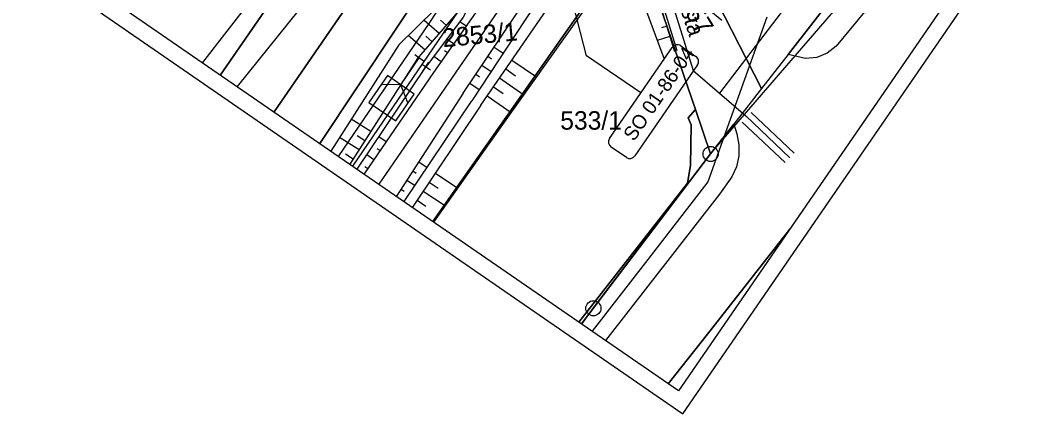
# Model space of a CAD drawing. Extents: x -558195 to -557985, y -1073457 to -1073198.
# Drawn here: x -558195.2 to -558102.7, y -1073456.6 to -1073420.3 of the extents above; entities that cross this region are included whole.
import ezdxf

# ---------------------------------------------------------------- set-up
doc = ezdxf.new("R2010")
doc.units = 0
for name, color, linetype in [('bubliny', 7, 'Continuous'), ('CETIN', 7, 'Continuous'), ('DWG-zabzař', 7, 'Continuous'), ('GasNet', 7, 'Continuous'), ('Kolej', 7, 'Continuous'), ('Komunikace', 7, 'Continuous'), ('Návěst místo trati', 7, 'Continuous'), ('Pasportizace VO Rapotín', 7, 'Continuous'), ('Plot - zábradlí', 7, 'Continuous'), ('Přejezd - štěrkové lože', 7, 'Continuous'), ('Rámeček', 7, 'Continuous'), ('Rámeček stavby', 7, 'Continuous'), ('Sonda - šrafa - vrstevnice', 7, 'Continuous'), ('Svazek obcí údolí Desné', 7, 'Continuous'), ('Svazek obcí-zabezpečovací', 7, 'Continuous'), ('Terén', 7, 'Continuous'), ('Vrstva 15', 7, 'Continuous'), ('Vrstva 18', 7, 'Continuous'), ('ŠPVS - kanalizace', 7, 'Continuous')]:
    doc.layers.add(name, color=color, linetype=linetype)

msp = doc.modelspace()

# ---------------------------------------------------------------- linework, layer by layer
at = {"layer": 'bubliny'}
for p, q in [((-558142.954, -1073423.635), (-558147.804, -1073404.729)), ((-558137.931, -1073427.051), (-558142.954, -1073423.635))]:
    msp.add_line(p, q, dxfattribs=at)
for points in [[(-558140.819, -1073431.245), (-558135.042, -1073422.858)], [(-558134.256, -1073422.713), (-558132.858, -1073423.675)], [(-558132.713, -1073424.462), (-558138.489, -1073432.85)], [(-558139.276, -1073432.995), (-558140.674, -1073432.032)]]:
    msp.add_lwpolyline(points, dxfattribs=at)
for centre, start, end in [((-558134.577, -1073423.179), 55.44273, 145.44273), ((-558133.179, -1073424.141), 325.44273, 55.44273), ((-558140.353, -1073431.566), 145.44273, 235.44273), ((-558138.955, -1073432.529), 235.44273, 325.44273)]:
    msp.add_arc(centre, 0.566, start, end, dxfattribs=at)
at = {"layer": 'CETIN'}
msp.add_lwpolyline([(-558151.47, -1073374.57), (-558151.89, -1073380.18), (-558153.51, -1073389.8), (-558157.95, -1073398.34), (-558171.64, -1073415.56), (-558178.389, -1073424.233)], dxfattribs=at)
at = {"layer": 'DWG-zabzař'}
msp.add_line((-558154.78, -1073419.51), (-558164.522, -1073433.785), dxfattribs=at)
at = {"layer": 'GasNet'}
msp.add_lwpolyline([(-558126.32, -1073420.06), (-558131.77, -1073435.23), (-558137.3, -1073442.38), (-558142.436, -1073448.999)], dxfattribs=at)
at = {"layer": 'Kolej'}
msp.add_lwpolyline([(-558162.085, -1073435.464), (-558155.66, -1073426.127), (-558147.216, -1073413.854), (-558143.692, -1073408.727), (-558141.06, -1073404.904), (-558137.302, -1073399.438), (-558134.569, -1073395.461), (-558131.717, -1073391.307), (-558124.893, -1073381.375), (-558115.4, -1073367.564), (-558106.183, -1073354.164), (-558097.487, -1073341.511), (-558095.261, -1073338.268), (-558090.946, -1073331.927), (-558084.696, -1073322.399), (-558079.035, -1073313.091), (-558076.876, -1073309.237)], dxfattribs=at)
at = {"layer": 'Komunikace'}
for points in [[(-558134.582, -1073423.154), (-558136.753, -1073416.165), (-558138.246, -1073411.366), (-558139.293, -1073408.016), (-558139.888, -1073406.031), (-558138.651, -1073404.246), (-558137.19, -1073402.13), (-558136.19, -1073405.354), (-558136.385, -1073405.515), (-558134.943, -1073410.228), (-558133.406, -1073415.122), (-558132.477, -1073418.012), (-558131.667, -1073419.37), (-558130.464, -1073420.348)], [(-558139.888, -1073406.031), (-558140.066, -1073406.285), (-558138.481, -1073411.422), (-558136.982, -1073416.266), (-558134.819, -1073423.23)]]:
    msp.add_lwpolyline(points, dxfattribs=at)
at = {"layer": 'Návěst místo trati'}
for p, q in [((-558157.974, -1073424.108), (-558158.798, -1073423.542)), ((-558160.086, -1073426.297), (-558158.386, -1073423.825)), ((-558158.179, -1073424.355), (-558157.355, -1073424.921)), ((-558158.05, -1073425.05), (-558157.484, -1073424.226))]:
    msp.add_line(p, q, dxfattribs=at)
for points in [[(-558160.086, -1073426.297), (-558161.322, -1073425.446), (-558163.023, -1073427.918), (-558160.551, -1073429.618), (-558158.851, -1073427.147), (-558160.086, -1073426.297)], [(-558159.419, -1073427.972), (-558160.086, -1073426.297), (-558161.89, -1073426.272)]]:
    msp.add_lwpolyline(points, dxfattribs=at)
at = {"layer": 'Pasportizace VO Rapotín'}
msp.add_lwpolyline([(-558143.374, -1073448.353), (-558142.291, -1073446.842), (-558131.5, -1073432.67), (-558118.796, -1073417.905), (-558090.893, -1073382.398), (-558083.8, -1073372.96), (-558076.467, -1073364.463), (-558070.931, -1073355.845), (-558066.74, -1073349.792), (-558061.514, -1073327.752)], dxfattribs=at)
for centre in [(-558131.5, -1073432.67), (-558142.318, -1073446.888)]:
    msp.add_circle(centre, 0.698, dxfattribs=at)
at = {"layer": 'Plot - zábradlí'}
for points in [[(-558150.682, -1073429.948), (-558139.407, -1073414.153), (-558135.827, -1073423.839)], [(-558157.022, -1073438.951), (-558150.682, -1073429.948)]]:
    msp.add_lwpolyline(points, dxfattribs=at)
at = {"layer": 'Přejezd - štěrkové lože'}
for p, q in [((-558154.06, -1073420.903), (-558154.641, -1073420.494)), ((-558154.635, -1073421.72), (-558154.877, -1073421.55)), ((-558155.211, -1073422.538), (-558155.837, -1073422.098)), ((-558155.786, -1073423.356), (-558156.046, -1073423.173)), ((-558151.481, -1073422.835), (-558150.644, -1073423.398)), ((-558156.362, -1073424.174), (-558157.034, -1073423.701)), ((-558152.597, -1073424.495), (-558151.744, -1073425.069)), ((-558152.039, -1073423.665), (-558151.701, -1073423.893)), ((-558153.156, -1073425.324), (-558152.811, -1073425.557)), ((-558153.714, -1073426.154), (-558152.843, -1073426.74)), ((-558161.433, -1073431.55), (-558162.106, -1073431.089)), ((-558162.563, -1073433.201), (-558163.227, -1073432.746)), ((-558161.998, -1073432.376), (-558162.265, -1073432.192)), ((-558158.431, -1073433.397), (-558157.648, -1073433.905)), ((-558163.128, -1073434.025), (-558163.392, -1073433.845)), ((-558158.975, -1073434.236), (-558158.667, -1073434.436)), ((-558159.519, -1073435.076), (-558158.764, -1073435.565)), ((-558160.063, -1073435.915), (-558159.767, -1073436.107))]:
    msp.add_line(p, q, dxfattribs=at)
for points in [[(-558142.117, -1073403.477), (-558143.754, -1073404.051), (-558146.162, -1073407.17), (-558149.304, -1073412.355), (-558152.838, -1073417.196), (-558154.313, -1073420.055), (-558157.793, -1073424.718)], [(-558142.117, -1073403.477), (-558145.099, -1073408.167), (-558148.507, -1073413.01), (-558157.055, -1073425.159)], [(-558154.327, -1073427.065), (-558145.987, -1073414.672), (-558140.875, -1073407.427)], [(-558140.875, -1073407.427), (-558141.298, -1073409.138), (-558145.289, -1073415.259), (-558153.522, -1073427.772)], [(-558164.119, -1073434.063), (-558157.793, -1073424.718)], [(-558157.055, -1073425.159), (-558163.463, -1073434.515)], [(-558154.327, -1073427.065), (-558160.485, -1073436.566)], [(-558159.769, -1073437.059), (-558153.522, -1073427.772)]]:
    msp.add_lwpolyline(points, dxfattribs=at)
at = {"layer": 'Rámeček'}
msp.add_lwpolyline([(-557985.145, -1073240.445), (-558046.292, -1073198.324), (-558195.203, -1073414.499), (-558134.056, -1073456.62)], close=True, dxfattribs=at)
at = {"layer": 'Rámeček stavby'}
msp.add_lwpolyline([(-558106.904, -1073288.53), (-558048.067, -1073329.06), (-558134.478, -1073454.503), (-558193.315, -1073413.973)], close=True, dxfattribs=at)
at = {"layer": 'Sonda - šrafa - vrstevnice'}
for p, q in [((-558156.536, -1073421.58), (-558157.964, -1073420.344)), ((-558155.881, -1073420.825), (-558156.428, -1073420.351)), ((-558157.845, -1073423.092), (-558159.396, -1073421.75)), ((-558135.548, -1073420.883), (-558136.04, -1073421.035)), ((-558157.191, -1073422.337), (-558157.787, -1073421.821)), ((-558135.252, -1073421.838), (-558136.431, -1073422.204)), ((-558149.839, -1073424.015), (-558147.563, -1073425.578)), ((-558150.406, -1073424.839), (-558149.501, -1073425.46)), ((-558150.972, -1073425.663), (-558148.725, -1073427.207)), ((-558151.538, -1073426.487), (-558150.645, -1073427.101)), ((-558152.104, -1073427.312), (-558149.887, -1073428.835)), ((-558162.858, -1073430.608), (-558164.647, -1073429.462)), ((-558163.397, -1073431.45), (-558164.112, -1073430.992)), ((-558163.937, -1073432.292), (-558165.723, -1073431.148)), ((-558164.476, -1073433.134), (-558165.19, -1073432.677)), ((-558156.895, -1073434.434), (-558154.821, -1073435.825)), ((-558157.453, -1073435.265), (-558156.63, -1073435.816)), ((-558158.01, -1073436.095), (-558155.973, -1073437.461)), ((-558158.567, -1073436.925), (-558157.759, -1073437.467))]:
    msp.add_line(p, q, dxfattribs=at)
at = {"layer": 'Svazek obcí údolí Desné'}
for points in [[(-558167.537, -1073431.708), (-558157.08, -1073415.91), (-558144.45, -1073397.61), (-558143.83, -1073396.83), (-558140.29, -1073392.34), (-558139.67, -1073391.56), (-558138.4, -1073389.94), (-558132.32, -1073380.12), (-558131.71, -1073378.11), (-558099.53, -1073332.65), (-558091.21, -1073321.1), (-558086.89, -1073315.11), (-558086.02, -1073313.63), (-558082.18, -1073306.93), (-558081.607, -1073305.978)], [(-558060.859, -1073320.27), (-558066.64, -1073329.29), (-558067.37, -1073328.67), (-558071.91, -1073335.47), (-558071.45, -1073339.78), (-558072.38, -1073341.74), (-558078.52, -1073350.81), (-558086.59, -1073345.2), (-558088.33, -1073347.7), (-558094.78, -1073357.07), (-558098.42, -1073362.32), (-558098.04, -1073362.58), (-558100.88, -1073366.68), (-558101.24, -1073366.41), (-558106.08, -1073373.34), (-558109.37, -1073371.06), (-558120.48, -1073382.36), (-558123.3, -1073385.22), (-558134.85, -1073401.19), (-558135.09, -1073403.23), (-558138.47, -1073412.32), (-558157.115, -1073438.887)]]:
    msp.add_lwpolyline(points, dxfattribs=at)
at = {"layer": 'Svazek obcí-zabezpečovací'}
msp.add_lwpolyline([(-558165.821, -1073432.89), (-558157.458, -1073420.639), (-558154.525, -1073416.12), (-558151.189, -1073413.898), (-558150.553, -1073413.027), (-558150.04, -1073412.321), (-558148.971, -1073410.618), (-558145.663, -1073405.43), (-558143.751, -1073404.04), (-558142.144, -1073403.55), (-558137.689, -1073396.948), (-558137.513, -1073396.367), (-558137.099, -1073393.941), (-558135.318, -1073390.256), (-558133.046, -1073387.072), (-558129.455, -1073381.095), (-558128.604, -1073379.498), (-558127.764, -1073378.874), (-558122.652, -1073382.89), (-558121.638, -1073382.251), (-558115.441, -1073375.378), (-558104.377, -1073360.537), (-558097.871, -1073351.756)], dxfattribs=at)
at = {"layer": 'Terén'}
for points in [[(-558152.696, -1073428.173), (-558144.227, -1073415.844), (-558139.347, -1073410.546), (-558136.982, -1073416.266)], [(-558160.273, -1073422.611), (-558156.919, -1073419.317), (-558153.676, -1073412.127)], [(-558158.606, -1073423.971), (-558154.771, -1073419.542), (-558153.233, -1073415.919), (-558151.605, -1073413.53)], [(-558160.273, -1073422.611), (-558166.526, -1073432.405)], [(-558158.606, -1073423.971), (-558164.779, -1073433.608)], [(-558152.696, -1073428.173), (-558159.008, -1073437.583)]]:
    msp.add_lwpolyline(points, dxfattribs=at)
at = {"layer": 'Vrstva 15'}
for points in [[(-558167.537, -1073431.708), (-558157.08, -1073415.91), (-558144.45, -1073397.61), (-558143.83, -1073396.83), (-558140.29, -1073392.34), (-558139.67, -1073391.56), (-558138.4, -1073389.94), (-558132.32, -1073380.12), (-558131.71, -1073378.11), (-558099.53, -1073332.65), (-558091.21, -1073321.1), (-558086.89, -1073315.11), (-558086.02, -1073313.63), (-558082.18, -1073306.93), (-558081.607, -1073305.978)], [(-558060.859, -1073320.27), (-558066.64, -1073329.29), (-558067.37, -1073328.67), (-558071.91, -1073335.47), (-558071.45, -1073339.78), (-558072.38, -1073341.74), (-558078.52, -1073350.81), (-558086.59, -1073345.2), (-558088.33, -1073347.7), (-558094.78, -1073357.07), (-558098.42, -1073362.32), (-558098.04, -1073362.58), (-558100.88, -1073366.68), (-558101.24, -1073366.41), (-558106.08, -1073373.34), (-558109.37, -1073371.06), (-558120.48, -1073382.36), (-558123.3, -1073385.22), (-558134.85, -1073401.19), (-558135.09, -1073403.23), (-558138.47, -1073412.32), (-558157.115, -1073438.887)], [(-558063.002, -1073350.77), (-558070.37, -1073360.66), (-558089.91, -1073385.65), (-558114.04, -1073415.6), (-558119.93, -1073422.75), (-558120.74, -1073423.38), (-558121.71, -1073423.79), (-558122.74, -1073423.86), (-558124.36, -1073423.51), (-558092.4, -1073382.52), (-558083.8, -1073372.96), (-558071.77, -1073359.59), (-558059.92, -1073343.2), (-558058.64, -1073341.4), (-558059.76, -1073344.95), (-558061.55, -1073348.53), (-558062.337, -1073349.804)], [(-558063.002, -1073350.77), (-558070.37, -1073360.66), (-558089.91, -1073385.65), (-558114.04, -1073415.6), (-558119.93, -1073422.75), (-558120.74, -1073423.38), (-558121.71, -1073423.79), (-558122.74, -1073423.86), (-558124.36, -1073423.51), (-558126.8, -1073426.64), (-558129.35, -1073429.91)], [(-558192.178, -1073414.734), (-558181.99, -1073399.3), (-558177.33, -1073402.38), (-558166.05, -1073409.92), (-558176.703, -1073425.394)], [(-558176.703, -1073425.394), (-558166.05, -1073409.92), (-558161.06, -1073413.25), (-558171.759, -1073428.8)], [(-558157.115, -1073438.887), (-558138.47, -1073412.32), (-558132.91, -1073428.56), (-558133.56, -1073429.34), (-558133.31, -1073429.98), (-558133.35, -1073433.74), (-558133.63, -1073435.37), (-558143.644, -1073448.167)], [(-558171.759, -1073428.8), (-558161.06, -1073413.25), (-558157.08, -1073415.91), (-558167.537, -1073431.708)], [(-558143.644, -1073448.167), (-558133.63, -1073435.37), (-558133.35, -1073433.74), (-558133.31, -1073429.98), (-558133.56, -1073429.34), (-558132.91, -1073428.56), (-558131.5, -1073432.67), (-558143.427, -1073448.316)], [(-558143.427, -1073448.316), (-558131.5, -1073432.67), (-558129.35, -1073429.91), (-558129.07, -1073430.81), (-558128.89, -1073431.83), (-558128.89, -1073432.84), (-558129.1, -1073433.85), (-558129.56, -1073434.77), (-558130.67, -1073436.36), (-558141.211, -1073449.842)], [(-558129.35, -1073429.91), (-558129.07, -1073430.81), (-558128.89, -1073431.83), (-558128.89, -1073432.84), (-558129.1, -1073433.85), (-558129.56, -1073434.77), (-558130.67, -1073436.36), (-558141.211, -1073449.842)], [(-558124.184, -1073439.587), (-558131.78, -1073449.27), (-558135.416, -1073453.834)], [(-558135.416, -1073453.834), (-558131.78, -1073449.27), (-558124.184, -1073439.587)]]:
    msp.add_lwpolyline(points, dxfattribs=at)
for points in [[(-558130.91, -1073418.65), (-558126.94, -1073419.09), (-558106.42, -1073391.52), (-558097.38, -1073379.37), (-558096.11, -1073380.17), (-558092.4, -1073382.52), (-558124.36, -1073423.51), (-558126.8, -1073426.64)], [(-558138.47, -1073412.32), (-558135.09, -1073403.23), (-558135.05, -1073407.29), (-558131.47, -1073417.12), (-558130.91, -1073418.65), (-558126.8, -1073426.64), (-558129.35, -1073429.91), (-558131.5, -1073432.67), (-558132.91, -1073428.56)]]:
    msp.add_lwpolyline(points, close=True, dxfattribs=at)
at = {"layer": 'ŠPVS - kanalizace'}
for p, q in [((-558166.162, -1073415.255), (-558175.164, -1073426.455)), ((-558127.758, -1073428.853), (-558123.786, -1073432.604)), ((-558128.582, -1073429.725), (-558124.638, -1073433.446))]:
    msp.add_line(p, q, dxfattribs=at)
for points in [[(-558083.612, -1073365.509), (-558130.675, -1073427.075)], [(-558142.53, -1073396.09), (-558141.8, -1073397.5), (-558137.42, -1073411.15), (-558133.1, -1073424.98)], [(-558133.1, -1073424.98), (-558128.25, -1073429.17), (-558124.187, -1073433.025)]]:
    msp.add_lwpolyline(points, dxfattribs=at)

# ---------------------------------------------------------------- texts
at = {"layer": 'bubliny'}
msp.add_text('SO 01-86-04', height=1.29937, rotation=55.44273, dxfattribs=at).set_placement((-558138.576, -1073431.583))
at = {"layer": 'Komunikace'}
msp.add_text('asf. cesta', height=1.5, rotation=288.07811, dxfattribs=at).set_placement((-558136.12, -1073413.781))
at = {"layer": 'Vrstva 18'}
for s, rotation, p in [('2857', 301.3577, (-558135.211, -1073417.522)), ('2853/1', 5.24304, (-558156.173, -1073422.836))]:
    msp.add_text(s, height=1.7, rotation=rotation, dxfattribs=at).set_placement(p)
msp.add_text('533/1', height=1.7, dxfattribs=at).set_placement((-558145.374, -1073430.431))

doc.saveas('drawing.dxf')
